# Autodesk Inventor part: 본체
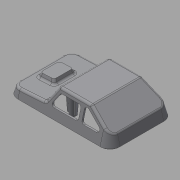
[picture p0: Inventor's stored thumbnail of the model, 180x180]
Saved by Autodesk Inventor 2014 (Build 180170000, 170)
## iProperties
Created: 2015-06
Part Number: 본체
Material: Generic
Document SubType Name: Modeling
Designer: Administrator
Density: 1 g/cm^3
Appearance: Default
Author: Administrator
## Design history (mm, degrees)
sketch "스케치2"
  geometry: L1 (-49, 38)-(49, 38); L2 (61, 26)-(61, -26); L3 (49, -38)-(-49, -38); L4 (-61, -26)-(-61, 26); L5 (-61, 38)-(61, -38); L6 (61, 38)-(-61, -38); A1 r 12 centre (-49, -26) between (-61, -26) and (-49, -38); A2 r 12 centre (-49, 26) between (-49, 38) and (-61, 26); A3 r 12 centre (49, 26) between (61, 26) and (49, 38); A4 r 12 centre (49, -26) between (49, -38) and (61, -26); 1 further point
  constraints: 12 end point, 8 point on circle, 8 point on line, 8 tangent, 4 centre point, 3 equal radius, 2 midpoint, 2 parallel, 1 horizontal, 1 perpendicular
  dimensions: "d0" = 122 distance of L5.end L6.end; "d1" = 76 distance of L6.start L5.end; "d2" = 12 radius of A1
extrude "돌출1" new body sketch "스케치2" distance "d3" = 30; taper "d4" = -15 deg
sketch "스케치3"
  geometry: L1 (-31, 30)-(-61, 30); L2 (-61, 30)-(-61, 10); L3 (-61, 10)-(-31, 30); L4 (49, 30)-(-49, 30) reference; 2 further points
  constraints: 6 end point, 1 collinear, 1 horizontal, 1 perpendicular, 1 vertical alignment
  dimensions: "d5" = 30 distance of L1.start L1.end; "d6" = 20 distance of L1.end L2.end
extrude "돌출2" cut sketch "스케치3" stored distance "d7" = 30; taper "d8" = 0 deg
sketch "스케치4"
  geometry: L1 (1.279, 39.573)-(19, 11.213); L2 (19, 11.213)-(69.975, 8.542); L3 (69.975, 8.542)-(59.484, 45.933); L4 (59.484, 45.933)-(1.279, 39.573); L5 (-49, 0)-(49, 0) reference; L6 (61, 0)-(52.962, 30) reference; 1 further point
  constraints: 8 end point, 1 point on line
  dimensions: "d9" = 3 deg angle of L5 L2; "d10" = 42 horizontal distance of L1.end L6.start; "d11" = 125 deg angle of L1 L2; "d12" = 9 distance from line of L6.start L2
extrude "돌출3" cut sketch "스케치4" stored distance "d13" = 30; taper "d14" = 0 deg
sketch "스케치5"
  geometry: L1 (-31.529, 47.995)-(-11.529, 47.995); L2 (-11.529, 47.995)-(-11.529, 21.995); L3 (-11.529, 21.995)-(-31.529, 21.995); L4 (-31.529, 21.995)-(-31.529, 47.995); L5 (-31.529, 47.995)-(-11.529, 21.995); L6 (-11.529, 47.995)-(-31.529, 21.995); L7 (-30.546, -3.005)-(67.32, -3.005) reference; L8 (-42.529, 60.995)-(-42.529, 8.995) reference; 2 further points
  constraints: 12 end point, 2 midpoint, 2 parallel, 1 horizontal, 1 perpendicular
  dimensions: "d15" = 20 distance of L2.end L3.end; "d16" = 26 distance of L1.end L2.end; "d17" = 38 distance from line of L7 point (-21.529, 34.995); "d18" = 21 distance from line of point (-21.529, 34.995) L8
extrude "돌출4" join sketch "스케치5" distance "d19" = 5; taper "d20" = -20 deg
fillet "모깎기1" dims "d21" = 3
fillet "모깎기2" dims "d22" = 3
fillet "모깎기3" dims "d23" = 3
feature "쉘1" dims "d24" = 2
sketch "스케치6"
  geometry: L1 (-49, 35.929)-(49, 35.929) reference; L2 (58.929, 26)-(58.929, -26) reference; L3 (49, -35.929)-(-49, -35.929) reference; L4 (-58.929, -26)-(-58.929, 26) reference; L5 (49, -38)-(-49, -38) reference; L6 (61, 26)-(61, -26) reference; L7 (-49, 38)-(49, 38) reference; L8 (-61, -26)-(-61, 26) reference; L9 (60, 26)-(60, -26); L10 (49, -37)-(-49, -37); L11 (-60, -26)-(-60, 26); L12 (-49, 37)-(49, 37); A1 r 9.929 centre (-49, 26) between (-49, 35.929) and (-58.929, 26) reference; A2 r 9.929 centre (49, 26) between (58.929, 26) and (49, 35.929) reference; A3 r 9.929 centre (49, -26) between (49, -35.929) and (58.929, -26) reference; A4 r 9.929 centre (-49, -26) between (-58.929, -26) and (-49, -35.929) reference; A5 r 12 centre (49, -26) between (49, -38) and (61, -26) reference; A6 r 12 centre (49, 26) between (61, 26) and (49, 38) reference; A7 r 12 centre (-49, 26) between (-49, 38) and (-61, 26) reference; A8 r 12 centre (-49, -26) between (-61, -26) and (-49, -38) reference; A9 r 11 centre (49, 26) between (60, 26) and (49, 37); A10 r 11 centre (49, -26) between (49, -37) and (60, -26); A11 r 11 centre (-49, -26) between (-60, -26) and (-49, -37); A12 r 11 centre (-49, 26) between (-49, 37) and (-60, 26); 1 further point
  constraints: 8 end point, 8 point on circle, 4 centre point, 7 other
  dimensions: "d25" = 1 distance between parallel lines of L7 L12
extrude "돌출5" join sketch "스케치6" distance "d26" = 1; taper "d27" = 0 deg
sketch "스케치7"
  geometry: L1 (18.172, 12.538)-(8.142, 28.59) reference; L2 (5.598, 30)-(-30.092, 30) reference; L3 (-31.756, 29.496)-(-50.664, 16.891) reference; L4 (10.994, 14.59)-(5.371, 23.59); L5 (2.826, 25)-(-17.138, 25); L6 (8.45, 10)-(-17.138, 10); L7 (-20.138, 22)-(-20.138, 13); L8 (-28.65, 25.557)-(-43.742, 15.496); L9 (-23.986, 23.061)-(-23.986, 13); L10 (-26.986, 10)-(-42.078, 10); A1 r 3 centre (-26.986, 23.061) between (-23.986, 23.061) and (-28.65, 25.557); A2 r 3 centre (-42.078, 13) between (-43.742, 15.496) and (-42.078, 10); A3 r 3 centre (-26.986, 13) between (-26.986, 10) and (-23.986, 13); A4 r 3 centre (-17.138, 22) between (-17.138, 25) and (-20.138, 22); A5 r 3 centre (2.826, 22) between (5.371, 23.59) and (2.826, 25); A6 r 3 centre (8.45, 13) between (8.45, 10) and (10.994, 14.59); A7 r 3 centre (-17.138, 13) between (-20.138, 13) and (-17.138, 10); 5 further points
  constraints: 14 end point, 14 point on circle, 14 tangent, 8 point on line, 7 centre point, 6 equal radius, 5 parallel, 2 perpendicular, 1 collinear
  dimensions: "d34" = 5 distance between parallel lines of L1 L4; "d35" = 5 distance between parallel lines of L2 L5; "d36" = 34 distance from line of L7 point (13.862, 10); "d37" = 15 distance of point (-20.138, 25) point (-20.138, 10); "d38" = 5 distance between parallel lines of L3 L8; "d41" = 28 distance from line of point (-51.986, 10) L9; "d42" = 3 radius of A1
extrude "돌출6" cut sketch "스케치7" stored distance "d43" = 1; taper "d44" = 0 deg
node "작업 평면1"
sketch "스케치8"
  geometry: A1 r 4 centre (-21, 0) between (-17, 0) and (-25, 0); A2 r 4 centre (-10, 0) between (-6, 0) and (-14, 0); A3 r 4 centre (10, 0) between (14, 0) and (6, 0); A4 r 4 centre (21, 0) between (25, 0) and (17, 0); 3 further points
  constraints: 8 point on circle, 4 centre point, 13 other
  dimensions: "d46" = 8 diameter of A1; "d47" = 8 diameter of A2; "d48" = 8 diameter of A3; "d49" = 8 diameter of A4; "d50" = 20 distance of A3.centre A2.centre; "d51" = 10 distance of point (0, 0) A2.centre; "d52" = 11 distance of A2.centre A1.centre; "d53" = 11 distance of A4.centre A3.centre
extrude "돌출7" join sketch "스케치8" stored distance "d54" = 1; taper "d55" = 0 deg
chamfer "모따기1" distance "d56" = 1; stored, may be unused: second distance "d57" = 2, angle "d58" = 45 deg
sketch "스케치9"
  geometry: C1 r 3 at (-40, 0); C2 r 3 at (0, 22); C3 r 3 at (40, 0); C4 r 3 at (0, -22); 1 further point
  constraints: 4 centre point, 2 horizontal alignment, 2 vertical alignment
  dimensions: "d59" = 6 diameter of C1; "d60" = 6 diameter of C2; "d61" = 6 diameter of C3; "d62" = 6 diameter of C4; "d63" = 40 distance of point (0, 0) C1.centre; "d64" = 40 distance of C3.centre point (0, 0); "d65" = 22 distance of C2.centre point (0, 0); "d66" = 44 distance of C2.centre C4.centre
extrude "돌출8" join sketch "스케치9" stored distance "d67" = 1; taper "d68" = 2 deg
sketch "스케치10"
  geometry: 1 further point
node "작업 평면2"
sketch "스케치12"
  geometry: L1 (-5, 23)-(5, 23); L2 (5, 23)-(5, 21); L3 (5, 21)-(-5, 21); L4 (-5, 21)-(-5, 23); L5 (-5, 23)-(5, 21); L6 (5, 23)-(-5, 21); L7 (35, 1)-(45, 1); L8 (45, 1)-(45, -1); L9 (45, -1)-(35, -1); L10 (35, -1)-(35, 1); L11 (35, 1)-(45, -1); L12 (45, 1)-(35, -1); L13 (-45, 1)-(-35, 1); L14 (-35, 1)-(-35, -1); L15 (-35, -1)-(-45, -1); L16 (-45, -1)-(-45, 1); L17 (-45, 1)-(-35, -1); L18 (-35, 1)-(-45, -1); L19 (-5, -21)-(5, -21); L20 (5, -21)-(5, -23); L21 (5, -23)-(-5, -23); L22 (-5, -23)-(-5, -21); L23 (-5, -21)-(5, -23); L24 (5, -21)-(-5, -23); C1 r 3 at (0, 22) reference; C2 r 3 at (-40, 0) reference; C3 r 3 at (0, -22) reference; C4 r 3 at (40, 0) reference; 1 further point
  constraints: 48 end point, 8 midpoint, 8 parallel, 4 horizontal, 4 perpendicular
  dimensions: "d70" = 2 distance of L19.end L20.end; "d71" = 2 distance of L9.end L7.start; "d72" = 2 distance of L1.end L2.end; "d73" = 2 distance of L13.end L14.end; "d74" = 10 horizontal distance of L13.end L15.end; "d75" = 10 distance of L2.end L3.end; "d76" = 10 distance of L19.start L19.end; "d77" = 10 distance of L7.start L7.end
extrude "돌출9" join sketch "스케치12" stored distance "d78" = 1; taper "d79" = 2.5 deg
sketch "스케치13"
  geometry: C1 r 3 at (0, 0) reference; C2 r 3 at (-80, 0) reference; C3 r 3 at (-40, 22) reference; C4 r 3 at (-40, -22) reference; 5 further points
  constraints: 4 coincident
hole "구멍1" sketch "스케치13" at (-80, 0), (-40, 22), (-40, -22), (0, 0) diameter "d80" = 3.242; stored, may be unused: countersink angle "d84" = 90 deg, drill point angle "d86" = 118 deg; dims "d81" = 9, "d82" = 4, "d83" = 2, "d85" = 11
node "솔리드1"
node "투영된 루프4"
node "투영된 루프5"
node "투영된 루프6"
node "투영된 루프7"
node "투영된 루프8"
node "투영된 루프9"
node "투영된 루프10"
other parameters: "d45" = -63, "d69" = 2
